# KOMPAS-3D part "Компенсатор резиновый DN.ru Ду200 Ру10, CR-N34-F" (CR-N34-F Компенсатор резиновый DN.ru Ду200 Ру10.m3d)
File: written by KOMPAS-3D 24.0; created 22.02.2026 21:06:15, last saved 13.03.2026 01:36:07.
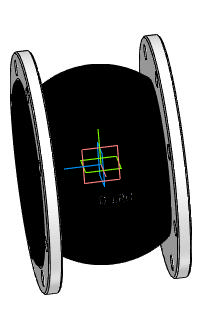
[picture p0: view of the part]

Document properties: Автор: DN.RU; Полное имя файла: CR-N34-F Компенсатор резиновый DN.ru Ду200 Ру10.cdw

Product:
- Body: Твердое тело2  | qty 1
    Масса: 47.364795
- Part/product: Компенсатор резиновый DN.ru Ду200 Ру10  | designation CR-N34-F
    Масса: 20
    Раздел спецификации: Прочие изделия
    Форматы листов документа: A2
    Комментарий: D140-02095
    Примечание: D140-02095
    additional columns: Типовые

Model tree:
1. Твердое тело2  (labels: Твердое тело2)

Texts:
  CR-N34-F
